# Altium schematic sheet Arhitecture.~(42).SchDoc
size A3; SheetNumber: 1; SheetTotal: 1
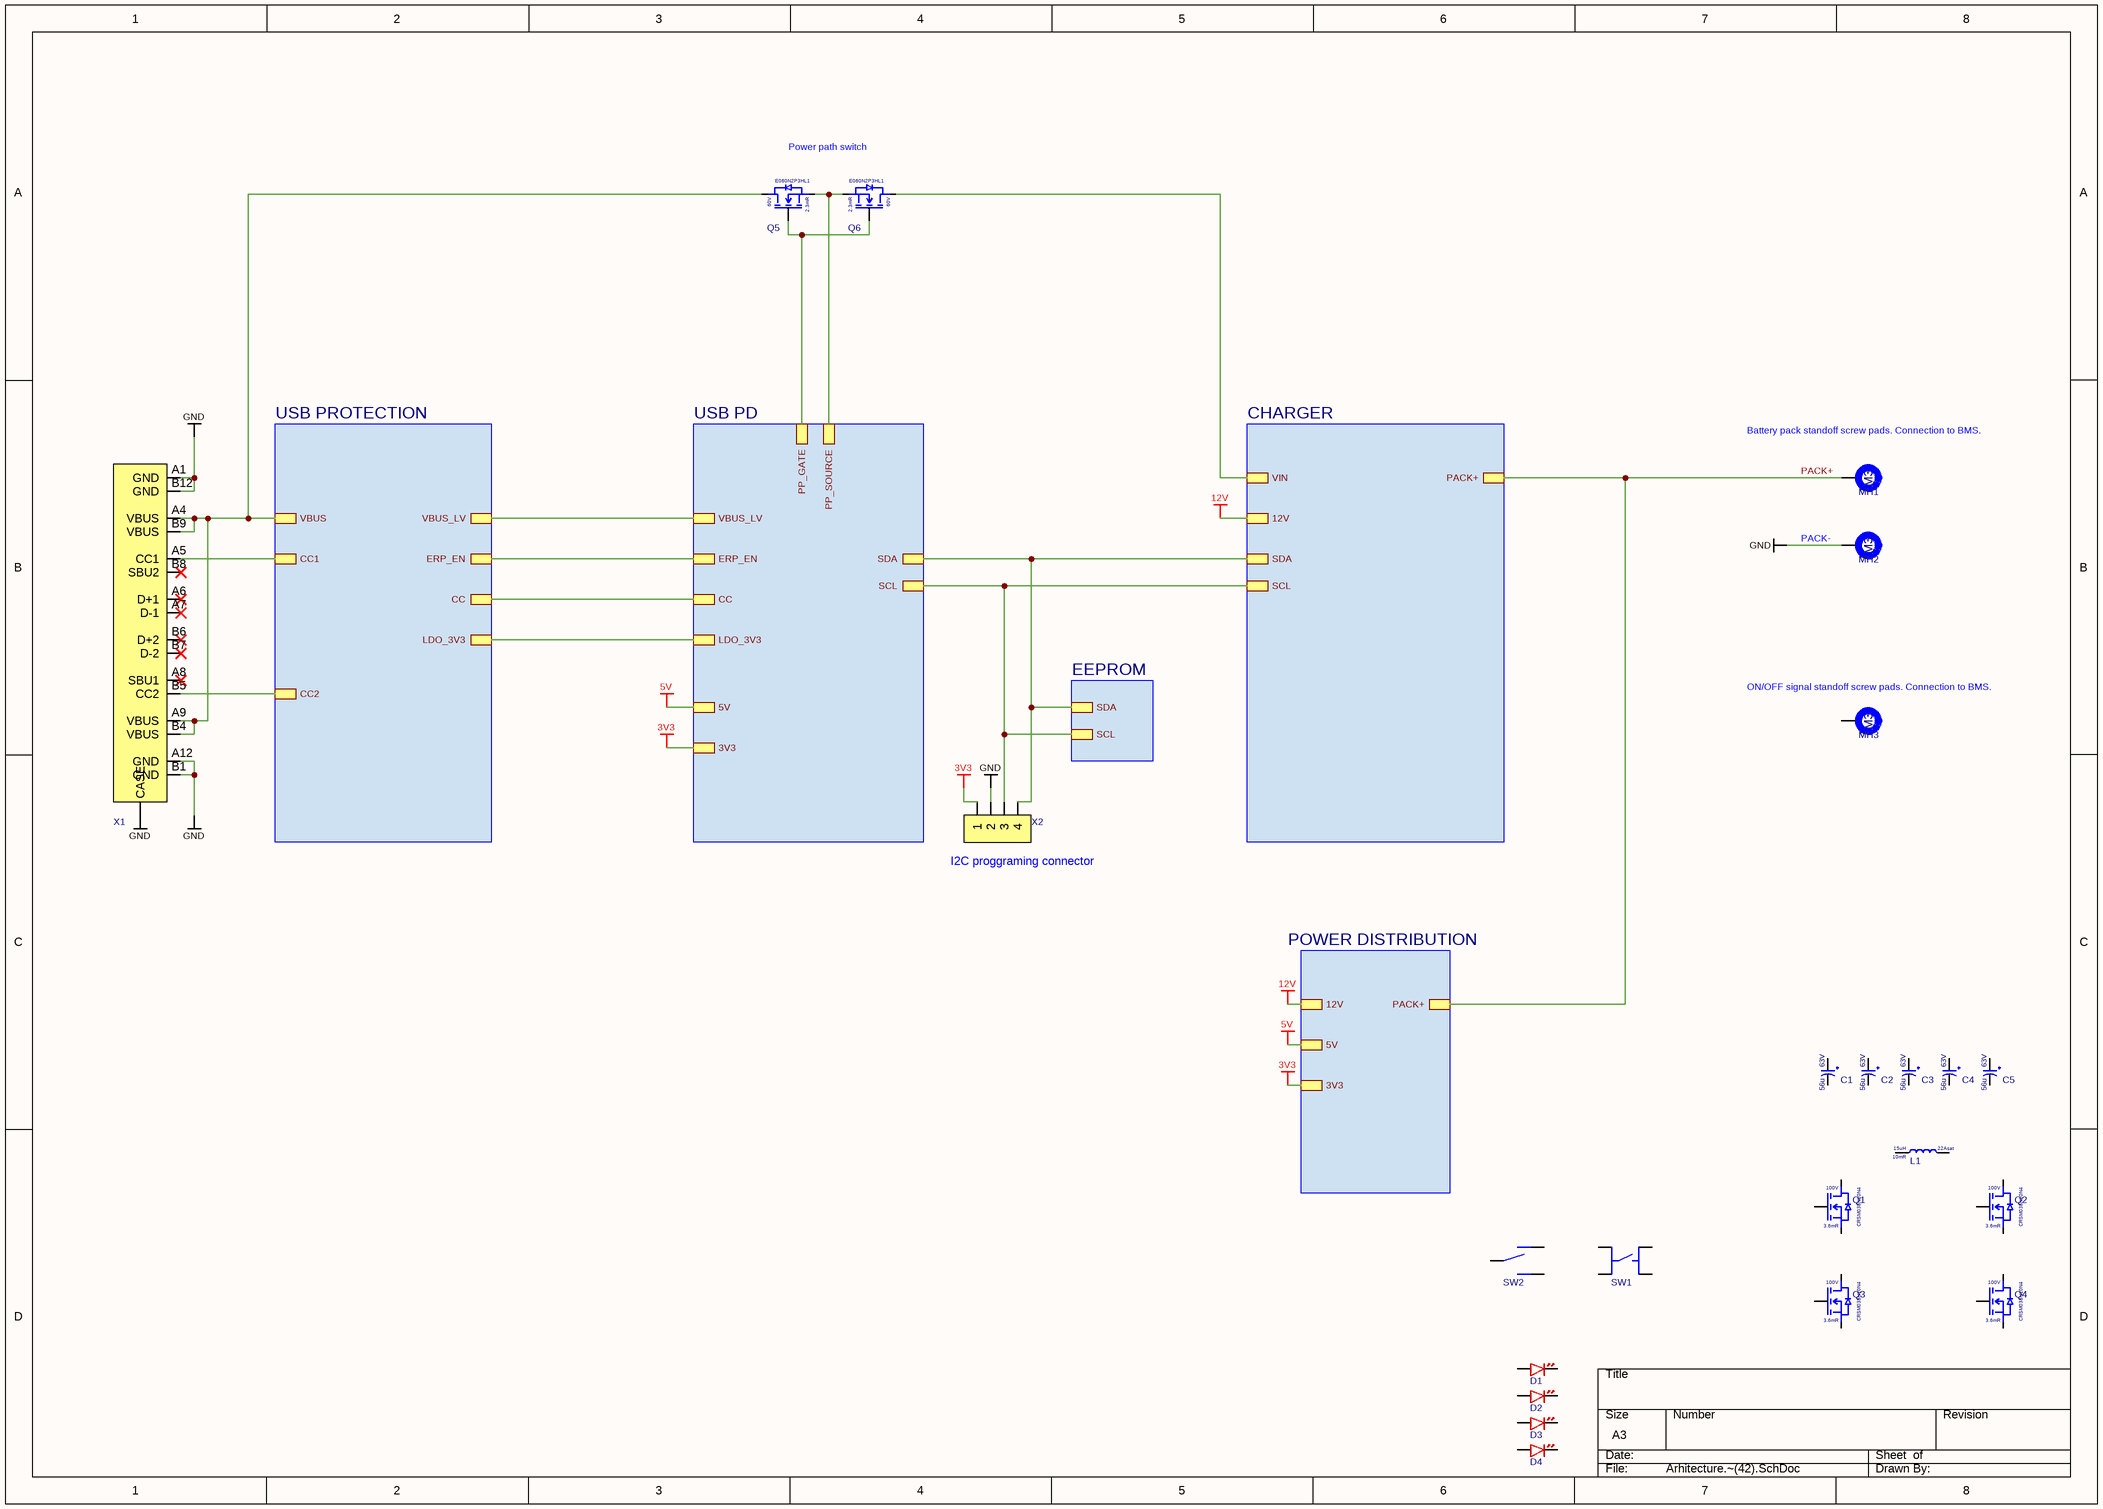
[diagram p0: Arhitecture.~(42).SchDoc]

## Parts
C1  Voltage Rating: 63V  Capacitance: 56u  [CAP_SMD_10X10.2]  (hidden comment: EEHZA1J560P)
C2  Voltage Rating: 63V  Capacitance: 56u  [CAP_SMD_10X10.2]  (hidden comment: EEHZA1J560P)
C3  Voltage Rating: 63V  Capacitance: 56u  [CAP_SMD_10X10.2]  (hidden comment: EEHZA1J560P)
C4  Voltage Rating: 63V  Capacitance: 56u  [CAP_SMD_10X10.2]  (hidden comment: EEHZA1J560P)
C5  Voltage Rating: 63V  Capacitance: 56u  [CAP_SMD_10X10.2]  (hidden comment: EEHZA1J560P)
D1  XL-1608SURC-06  [DIODE_0603]  (value not drawn)
D2  XL-1608SURC-06  [DIODE_0603]  (value not drawn)
D3  XL-1608SURC-06  [DIODE_0603]  (value not drawn)
D4  XL-1608SURC-06  [DIODE_0603]  (value not drawn)
L1  Resistance: 10mR  Saturation current: 22Asat  Inductance: 15uH  [MTF1810-150M]  (hidden comment: MTF1810-150M)
MH1  Hole size: M3  [M3 Plated]  (hidden comment: M?)  (no BOM)
MH2  Hole size: M3  [M3 Plated]  (hidden comment: M?)  (no BOM)
MH3  Hole size: M3  [M3 Plated]  (hidden comment: M?)  (no BOM)
Q1  Rds: 3.6mR  Voltage: 100V  [DFN-8 (5x6)]  (hidden comment: CRSM038N10N4)
Q2  Rds: 3.6mR  Voltage: 100V  [DFN-8 (5x6)]  (hidden comment: CRSM038N10N4)
Q3  Rds: 3.6mR  Voltage: 100V  [DFN-8 (5x6)]  (hidden comment: CRSM038N10N4)
Q4  Rds: 3.6mR  Voltage: 100V  [DFN-8 (5x6)]  (hidden comment: CRSM038N10N4)
Q5  Rds: 2.3mR  Voltage: 60V  [DFN-8 (5x6)]  (hidden comment: E060N2P3HL1)
Q6  Rds: 2.3mR  Voltage: 60V  [DFN-8 (5x6)]  (hidden comment: E060N2P3HL1)
SW1  TS4560TP  [TS4560TP]  (value not drawn)
SW2  SS-3235S-L3  [SS-3235S-L3]  (value not drawn)
X1  TYPE-C 16P LTH6.8  [TYPE-C 16P LTH6.8]  (value not drawn)
X2  B4B-PH-K-S(LF)(SN)  [B4B-PH-K-S(LF)(SN)]  (value not drawn)

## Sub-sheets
CHARGER = Charger.SchDoc: PACK+, VIN, SDA, SCL, 12V
EEPROM = EEPROM.SchDoc: SDA, SCL
POWER DISTRIBUTION = Power distribution.SchDoc: PACK+, 12V, 5V, 3V3
USB PD = USB PD.SchDoc: VBUS_LV, ERP_EN, CC, LDO_3V3, PP_GATE, PP_SOURCE, SDA, SCL, 5V, 3V3
USB PROTECTION = USB protection.SchDoc: VBUS, CC1, CC2, VBUS_LV, ERP_EN, CC, LDO_3V3

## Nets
3V3: X2.1 ; sheet POWER DISTRIBUTION/3V3, sheet USB PD/3V3
5V: sheet POWER DISTRIBUTION/5V, sheet USB PD/5V
12V: sheet CHARGER/12V, sheet POWER DISTRIBUTION/12V
GND: MH2.1 X1.A1(GND) X1.A12(GND) X1.B1(GND) X1.B12(GND) X1.CASE X2.2
PACK+: MH1.1 ; sheet CHARGER/PACK+, sheet POWER DISTRIBUTION/PACK+
NetQ5_D: Q5.D X1.A4(VBUS) X1.A9(VBUS) X1.B4(VBUS) X1.B9(VBUS) ; sheet USB PROTECTION/VBUS
NetQ5_G: Q5.G Q6.G ; sheet USB PD/PP_GATE
NetQ5_S: Q5.S Q6.S ; sheet USB PD/PP_SOURCE
NetQ6_D: Q6.D ; sheet CHARGER/VIN
NetX1_A5: X1.A5(CC1) ; sheet USB PROTECTION/CC1
NetX1_B5: X1.B5(CC2) ; sheet USB PROTECTION/CC2
NetX2_3: X2.3 ; sheet CHARGER/SCL, sheet EEPROM/SCL, sheet USB PD/SCL
NetX2_4: X2.4 ; sheet CHARGER/SDA, sheet EEPROM/SDA, sheet USB PD/SDA
(unnamed): sheet USB PD/VBUS_LV, sheet USB PROTECTION/VBUS_LV
(unnamed): sheet USB PD/ERP_EN, sheet USB PROTECTION/ERP_EN  [a separate net that carries the same name]
(unnamed): sheet USB PD/CC, sheet USB PROTECTION/CC  [a separate net that carries the same name]
(unnamed): sheet USB PD/LDO_3V3, sheet USB PROTECTION/LDO_3V3  [a separate net that carries the same name]

Not connected (* = marked no-connect by the designer): C1 + -; C2 + -; C3 + -; C4 + -; C5 + -; D1 A K; D2 A K; D3 A K; D4 A K; L1 1 2; MH3 1; Q1 D G S; Q2 D G S; Q3 D G S; Q4 D G S; SW1 1 2 3 4; SW2 1 2 3; X1 A6(D+1)* A7(D-1)* A8(SBU1)* B6(D+2)* B7(D-2)* B8(SBU2)*

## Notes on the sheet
- Power path switch
- (near MH1) Battery pack standoff screw pads. Connection to BMS.
- (near MH2) PACK-
- (near MH3) ON/OFF signal standoff screw pads. Connection to BMS.
- (near X2) I2C proggraming connector

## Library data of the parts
C1-C5 = EEHZA1J560P: Cap AL-EL 56uF 63V 30mR 1.8Ar SMD 10x10.2mm; Manufacturer: Panasonic
D1-D4 = XL-1608SURC-06: LED Red 0603 25mA; Manufacturer: Xinglight
L1 = MTF1810-150M: Inductor 15uH 22Asat 10mR SMD 18x18x9 mm; Manufacturer: COILMX
MH1-MH3 = Mounting hole: Generic mounting hole symbol
Q1-Q4 = CRSM038N10N4: Nmos 100V 100A 3.6mR DFN-8(5x6); Manufacturer: CRMICRO
Q5 Q6 = E060N2P3HL1: Nmos 60V 180A 2.3mR PDFN5x6-8; Manufacturer: Existar
SW1 = TS4560TP: Switch Tactile SMD 4.5x4.5mm 6mmH SPST; Manufacturer: Shou Han
SW2 = SS-3235S-L3: Switch Slide SMD 9.1x3.5mm 6.6mmH; Manufacturer: XKB Connection
X1 = TYPE-C 16P LTH6.8: USB-C 16P SMD Vertical 6.50mmH; Manufacturer: Shou Han
X2 = B4B-PH-K-S(LF)(SN): Pin header 1x4 2.00mmP THT Vertical JST PH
